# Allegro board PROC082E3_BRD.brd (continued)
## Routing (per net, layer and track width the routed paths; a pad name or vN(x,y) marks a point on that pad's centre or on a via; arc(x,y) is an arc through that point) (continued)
CSI_TX_D3_P: length 35
  TOP w0.102: v1(39.94,187.75) 39.92,187.75 arc(39.71,187.66) 39.62,187.45 39.62,186.72 arc(39.52,186.22) 39.24,185.8 arc(38.12,185.05) 36.79,184.78 35.97,184.78 arc(34.2,184.43) 32.7,183.43 28.18,178.91 arc(26.85,176.93) 26.39,174.59 26.39,171.31 arc(26.23,170.93) 25.85,170.77 25.69,170.77 arc(25.52,170.69) 25.44,170.52 v1(25.44,170.45)
  BOTTOM w0.102: v1(39.94,187.75) 39.85,187.75 arc(39.7,187.81) 39.64,187.96 39.64,188.16 arc(39.65,188.19) 39.67,188.23 39.73,188.28 arc(39.75,188.32) 39.76,188.36 J20.21 ; U32.29 28.85,165.81 arc(28.81,165.82) 28.78,165.84 28.72,165.9 arc(28.69,165.92) 28.65,165.93 28.5,165.93 arc(28.3,165.97) 28.13,166.08 27.2,167.01 arc(26.93,167.42) 26.84,167.89 26.84,170.13 arc(26.65,170.59) 26.19,170.77 25.62,170.77 arc(25.6,170.77) 25.59,170.77 arc(25.48,170.71) 25.44,170.6 v1(25.44,170.45)
DOUT_N: length 5.1
  BOTTOM w0.102: U32.13 35.01,165.31 arc(35.04,165.3) 35.08,165.28 35.13,165.22 arc(35.17,165.2) 35.21,165.19 38.39,165.19 arc(38.65,165.25) 38.87,165.39 C406.2
DOUT_P: length 5.1
  BOTTOM w0.102: C405.2 38.86,164.74 arc(38.65,164.88) 38.41,164.93 35.21,164.93 arc(35.17,164.92) 35.13,164.9 35.08,164.84 arc(35.04,164.82) 35.01,164.81 U32.14
EEPROM_A0: length 4
  BOTTOM w0.152: U20.1 10.32,89.36 10.2,89.23 R152.1 R151.2
EEPROM_A1: length 3.2
  BOTTOM w0.152: U20.2 R148.1 R149.2
EEPROM_A2: length 3.2
  BOTTOM w0.152: R146.2 R147.1 U20.3
EEPROM_WP: length 1.9
  BOTTOM w0.152: R153.2 U20.7
GPIO0_HUB1: length 5.1
  BOTTOM w0.152: R204.2 40.79,118.95 40.74,118.9 38.73,118.9 38.18,119.45 38.18,119.69 37.7,120.16 U9.6
GPIO0_HUB2: length 4.9
  BOTTOM w0.152: R202.2 42.99,54.52 42.72,54.78 42.72,56.62 43.83,57.72 U24.6
GPIO0_HUB3: length 4.2
  BOTTOM w0.152: R200.2 24.1,59.19 23.68,58.78 22.44,58.78 22.13,59.08 22.13,59.31 21.51,59.94 U25.6
GPIO1_HUB1: length 6.3
  BOTTOM w0.152: U9.7 37.62,119.66 37.84,119.44 37.84,119.24 38.66,118.41 41.93,118.41 42.46,118.95 R205.2
GPIO1_HUB2: length 6.3
  BOTTOM w0.152: R203.2 43,53.2 42.39,53.8 42.39,56.79 43.33,57.72 U24.7
GPIO1_HUB3: length 5.5
  BOTTOM w0.152: U25.7 21.54,59.44 21.77,59.21 21.77,58.85 22.22,58.4 24.59,58.4 25.14,58.95 R201.2
HUB1_CK_O: length 5.8
  BOTTOM w0.152: U9.14 37.67,116.16 38.12,116.61 41.74,116.61 41.87,116.74 TP11.1
HUB1_CMLOUT0N: length 8.3
  BOTTOM w0.102: TP9.1 14.55,124.66 14.69,124.8 15.96,124.8 17.67,123.1 19.37,123.1 R96.1 19.73,122.75 20.02,123.05 20.38,123.05 C181.1
HUB1_CMLOUT0P: length 8.4
  BOTTOM w0.102: TP10.1 14.55,125.21 14.69,125.07 16.07,125.07 17.78,123.37 19.38,123.37 R96.2 19.73,123.71 20.02,123.41 20.28,123.41 C179.1
HUB1_CMLOUT1N: length 4.6
  BOTTOM w0.102: C167.1 21.08,126.38 20.98,126.48 20.29,126.48 19.95,126.15 R82.1 19.88,126.15 19.52,126.5 18.4,126.5 18.23,126.33 TP4.1
HUB1_CMLOUT1P: length 4.5
  BOTTOM w0.102: C166.1 21.08,126.85 20.98,126.74 20.29,126.74 R82.2 19.86,127.13 19.51,126.77 18.37,126.77 18.23,126.9 TP3.1
HUB1_CMLOUT2N: length 6.5
  BOTTOM w0.102: C178.1 40.4,124.6 40.5,124.7 41.41,124.7 R94.1 41.82,124.34 42.17,124.7 42.77,124.7 43.03,124.96 43.03,125.57 43.43,125.97 44.17,125.97 44.27,125.87 TP6.1
HUB1_CMLOUT2P: length 6.5
  BOTTOM w0.102: TP5.1 44.27,126.34 44.17,126.24 43.32,126.24 42.76,125.68 42.76,125.07 42.66,124.97 42.19,124.97 41.83,125.32 R94.2 41.41,124.97 40.5,124.97 40.4,125.07 C171.1
HUB1_CMLOUT3N: length 5.7
  BOTTOM w0.102: C182.1 40.38,121.53 40.62,121.77 41.22,121.77 R98.1 41.61,121.41 41.97,121.77 42.95,121.77 43.11,121.61 44.15,121.61 44.26,121.5 44.26,120.63 TP8.1
HUB1_CMLOUT3P: length 5.6
  BOTTOM w0.102: TP7.1 44.26,121.97 44.15,121.87 43.22,121.87 43.06,122.04 41.96,122.04 41.61,122.39 R98.2 41.22,122.04 40.62,122.04 40.38,122.27 C180.1
HUB1_I2C_SCL2: length 4.8
  BOTTOM w0.152: R87.1 38.24,126.23 37.03,125.01 37.03,124.6 36.73,124.31 36.12,124.31 35.82,124.01 U9.87
HUB1_I2C_SDA2: length 5.2
  BOTTOM w0.152: U9.88 36.32,123.65 36.62,123.95 36.94,123.95 37.43,124.44 37.43,124.83 38.91,126.31 38.91,126.7 39.06,126.84 R86.1
HUB1_IDX: length 8.7
  TOP w0.152: R16.1 24.77,124.77 25.01,124.53 R15.2 v1(25.01,123.47)
  L6_SIG2 w0.102: v1(25.01,123.47) 25.95,123.47 27.22,124.74 29.83,124.74 v1(30.32,124.24)
  BOTTOM w0.152: v1(30.32,124.24) U9.76
HUB1_INTBN: length 106.8
  TOP w0.152: v1(53.42,35.31) 53.01,35.31 52.59,35.73 J2.6
  L03_SIG1 w0.102: v1(46.84,112.37) 45.16,114.05 45.16,114.63 41.38,118.41 39.25,118.41 v1(38.02,117.19)
  L6_SIG2 w0.102: v1(53.42,35.31) 56.64,38.53 56.64,45.48 56.04,46.08 56.04,47.57 56.64,48.18 56.64,67.69 61.77,72.82 61.77,74.73 62.41,75.36 62.41,86.92 58.63,90.69 56.86,90.69 48.54,99.01 48.54,100.79 46.15,103.17 46.15,106.81 46.84,107.49 v1(46.84,112.37)
  BOTTOM w0.152: U9.9 37.76,118.66 38.72,117.71 R99.1 v1(38.02,117.19)
HUB1_LPF: length 1.6
  TOP w0.152: v1(30.82,122.58) 30.82,122.29 30.89,122.22 C30.1
  BOTTOM w0.152: v1(30.82,122.58) 30.82,122.69 30.82,122.7 U9.77
HUB1_MODE: length 5.4
  TOP w0.152: R13.2 31.78,126.97 v1(32.02,126.73)
  BOTTOM w0.152: R88.1 31.83,126.92 v1(32.02,126.73) 32.48,126.27 32.48,124.57 31.82,123.91 U9.79
HUB1_REF CLK: length 58.7
  L6_SIG2 w0.102: v1(40.06,108.46) 40.06,107.04 36.51,103.49 28.36,103.49 v1(27.01,102.14)
  BOTTOM w0.152: U9.15 37.67,115.66 38.32,116.31 41.5,116.31 42.16,115.65 42.98,115.65 43.21,115.42 43.21,113.46 40.64,110.9 40.64,109.04 v1(40.06,108.46) ; v1(27.01,102.14) 25.11,102.14 21.49,98.52 20.99,98.52 19.79,97.32 19.79,96.69 16.78,93.69 16.78,85.95 14.28,83.44 R156.2
HUB1_REF CLK_R: length 2.6
  BOTTOM w0.152: U22.13 16.21,79.77 15.92,80.07 14.91,80.07 14.31,80.67 R156.1
HUB1_RIN0_N: length 8.7
  TOP w0.13: v1(28.03,128.04) 27.82,128.26 arc(27.79,128.3) 27.78,128.35 27.78,131.19 arc(27.84,131.34) 27.99,131.4 C132.2
  BOTTOM w0.13: v1(28.03,128.04) 27.82,127.83 arc(27.79,127.78) 27.78,127.74 27.78,123.45 U9.71
HUB1_RIN0_P: length 8.7
  TOP w0.13: v1(27.12,128.04) 27.33,128.26 arc(27.36,128.3) 27.37,128.35 27.37,131.19 arc(27.31,131.34) 27.16,131.4 C126.1
  BOTTOM w0.13: v1(27.12,128.04) 27.33,127.83 arc(27.36,127.78) 27.37,127.74 27.37,123.45 U9.70
HUB1_RIN1_N: length 9.2
  TOP w0.13: C160.2 31.09,131.3 arc(30.94,131.24) 30.88,131.09 30.88,129.67 arc(30.82,129.36) 30.65,129.1 30.15,128.6 arc(30.09,128.51) 30.07,128.41 30.07,128.22 arc(30.08,128.17) 30.11,128.13 v1(30.32,127.91)
  BOTTOM w0.13: v1(30.32,127.91) 30.18,127.77 arc(30.15,127.73) 30.14,127.68 30.14,126.88 30.14,125.21 arc(30.09,124.93) 29.93,124.69 29.36,124.13 arc(29.3,124.04) 29.28,123.93 29.28,123.45 U9.74
HUB1_RIN1_P: length 9.2
  TOP w0.13: v1(29.41,127.91) 29.62,128.13 arc(29.65,128.17) 29.66,128.22 29.66,128.41 arc(29.71,128.67) 29.86,128.89 30.36,129.39 arc(30.44,129.51) 30.47,129.67 30.47,131.06 arc(30.4,131.23) 30.24,131.3 C161.2
  BOTTOM w0.13: U9.73 28.87,123.45 28.87,123.93 arc(28.92,124.19) 29.07,124.42 29.64,124.98 arc(29.71,125.09) 29.73,125.21 29.73,126.88 29.73,127.34 arc(29.7,127.52) 29.59,127.67 29.44,127.82 arc(29.42,127.86) v1(29.41,127.91)
HUB1_RIN2_N: length 11.9
  TOP w0.13: v1(33.53,128.4) 33.42,128.4 arc(33.26,128.46) 33.19,128.62 33.19,130.29 arc(33.54,131.12) 34.38,131.47 36.26,131.47 arc(36.39,131.42) 36.44,131.29 C198.2
  BOTTOM w0.13: U9.82 33.24,123.49 33.24,128.36 arc(33.33,128.48) 33.47,128.45 v1(33.53,128.4)
HUB1_RIN2_P: length 12
  TOP w0.13: C190.1 36.44,132.19 arc(36.35,131.97) 36.12,131.88 34.38,131.88 arc(33.25,131.41) 32.79,130.29 32.79,128.8 arc(32.74,128.58) v1(32.62,128.4)
  BOTTOM w0.13: U9.81 32.83,123.42 32.83,127.93 arc(32.79,128.16) 32.66,128.36 v1(32.62,128.4)
HUB1_RIN3_N: length 9
  TOP w0.13: v1(35.03,126.95) 34.79,126.95 arc(34.69,126.99) 34.64,127.1 34.64,127.8 arc(34.84,128.28) 35.32,128.48 37.51,128.48 arc(37.65,128.42) 37.71,128.28 C218.1
  BOTTOM w0.13: U9.85 34.74,123.49 34.74,126.83 arc(34.85,126.99) v1(35.03,126.95)
HUB1_RIN3_P: length 9.1
  TOP w0.13: C219.1 37.71,129.09 arc(37.65,128.95) 37.5,128.89 35.32,128.89 arc(34.55,128.57) 34.23,127.8 34.23,127.23 arc(34.2,127.08) v1(34.12,126.95)
  BOTTOM w0.13: U9.84 34.33,123.41 34.33,126.55 arc(34.3,126.72) 34.2,126.87 v1(34.12,126.95)
HUB1_SYNC: length 113.6
  TOP w0.152: v1(56.41,34.95) 56.13,34.66 48.64,34.66 48.09,35.22 J2.18
  L03_SIG1 w0.102: v1(46.91,113.41) 41.55,118.77 36.68,118.77 v1(36.29,119.16)
  L6_SIG2 w0.102: v1(46.91,113.41) 47.45,112.88 47.45,107.7 46.46,106.71 46.46,103.45 49.3,100.61 49.3,98.75 57.02,91.03 58.85,91.03 62.81,87.07 62.81,73.28 59.66,70.12 59.66,65.63 58.22,64.19 58.22,61.34 57.73,60.86 57.73,36.27 v1(56.41,34.95)
  BOTTOM w0.152: v1(36.29,119.16) U9.8
HUB2_CK_O: length 6.5
  BOTTOM w0.152: TP26.1 40,52.89 40,57.56 39.83,57.73 U24.14
HUB2_CMLOUT0N: length 9.6
  BOTTOM w0.102: C249.1 45.8,75.05 45.9,75.16 45.9,76.03 R161.1 45.54,76.45 45.9,76.81 45.9,82.46 45.8,82.56 TP14.1
HUB2_CMLOUT0P: length 9.6
  BOTTOM w0.102: C248.1 46.27,75.05 46.17,75.16 46.17,76.03 R161.2 46.52,76.49 46.17,76.84 46.17,82.46 46.27,82.56 TP13.1
HUB2_CMLOUT1N: length 6.2
  BOTTOM w0.102: TP16.1 49.73,79.23 49.84,79.13 49.84,76.75 R160.1 49.84,76.03 49.84,75.16 49.73,75.05 C247.1
HUB2_CMLOUT1P: length 6.2
  BOTTOM w0.102: TP15.1 50.2,79.23 50.1,79.13 50.1,76.75 R160.2 50.1,76.03 50.1,75.16 50.2,75.05 C246.1
HUB2_CMLOUT2N: length 5.5
  BOTTOM w0.102: TP28.1 51.96,49.9 52.19,50.12 52.19,51.52 R185.1 52.19,52.24 52.19,53.4 52.09,53.5 C306.1
HUB2_CMLOUT2P: length 5.5
  BOTTOM w0.102: C305.1 52.56,53.5 52.46,53.4 52.46,52.24 R185.2 52.46,51.52 52.46,50.12 52.69,49.9 TP27.1
HUB2_CMLOUT3N: length 5.5
  BOTTOM w0.102: TP30.1 46.45,49.9 46.68,50.12 46.68,51.52 R186.1 46.68,52.24 46.68,53.4 46.58,53.5 C308.1
HUB2_CMLOUT3P: length 5.5
  BOTTOM w0.102: TP29.1 47.17,49.9 46.95,50.12 46.95,51.52 R186.2 46.95,52.24 46.95,53.4 47.05,53.5 C307.1
HUB2_I2C_SCL2: length 3.6
  BOTTOM w0.152: R176.1 48.65,57.99 48.19,58.46 48.19,59.34 47.97,59.57 U24.87
HUB2_I2C_SDA2: length 3.7
  BOTTOM w0.152: U24.88 47.63,59.07 47.79,58.91 47.79,58.23 49.19,56.83 R179.1
HUB2_IDX: length 13.3
  TOP w0.152: R34.1 52.32,71.66 R37.2 51.21,71.63 50.58,71 48.4,71 47.93,70.53 v1(47.93,64.51)
  BOTTOM w0.152: v1(47.93,64.51) 47.93,64.76 47.62,65.07 U24.76
HUB2_INTBN: length 30.6
  TOP w0.152: J2.8 v1(52.09,38.22)
  L6_SIG2 w0.102: v1(52.09,38.22) 51.41,38.9 48.24,38.9 46.8,40.34 46.8,51.48 41.51,56.76 v1(40.41,56.76)
  BOTTOM w0.152: U24.9 42.33,57.81 42.17,57.66 41.48,57.66 41.13,57.31 R180.1 v1(40.41,56.76)
HUB2_LPF: length 2.4
  TOP w0.254: v1(46.14,65.14) 46.19,65.18 C93.1
  BOTTOM w0.152: v1(46.14,65.14) 46.14,64.75 46.32,64.57 U24.77
HUB2_MODE: length 16
  TOP w0.152: v1(47.94,63.71) 47.95,63.71 48.33,64.1 48.33,68.29 48.65,68.6 53.21,68.6 54.52,69.91 54.52,71.58 54.37,71.73 R38.2 53.88,71.73 R35.1
  BOTTOM w0.152: U24.79 47.79,63.57 v1(47.94,63.71)
HUB2_REF CLK: length 45.7
  BOTTOM w0.152: R155.2 17.47,83.03 17.69,83.26 20.06,83.26 28.44,74.88 28.44,73.69 29.58,72.55 29.58,66.89 29.32,66.63 29.32,64.96 29.83,64.45 29.83,61.43 31.56,59.7 31.56,58.1 34.66,55 38.9,55 39.52,55.63 39.52,57.12 39.33,57.32 U24.15
HUB2_REF CLK_R: length 2
  BOTTOM w0.152: U22.15 17.21,80.69 17.47,80.94 R155.1
HUB2_SYNC: length 39.8
  TOP w0.152: J2.22 46.59,35.6 46.24,35.24 v1(43.55,35.24)
  BOTTOM w0.152: U24.8 42.83,57.72 42.06,56.96 42.06,50.77 41.29,50 36.21,50 35.27,49.06 35.27,38.74 38.77,35.24 v1(43.55,35.24)
HUB3_CK_O: length 4.5
  BOTTOM w0.152: U25.14 24.03,55.94 24.04,55.94 TP23.1
HUB3_CMLOUT0N: length 4.8
  BOTTOM w0.102: TP24.1 4.2,55.48 3.76,55.92 3.76,57.18 R177.1 3.76,57.9 3.76,58.51 3.98,58.72 C298.1
HUB3_CMLOUT0P: length 4.8
  BOTTOM w0.102: C299.1 3.28,58.72 3.5,58.51 3.5,57.9 R177.2 3.5,57.18 3.5,55.77 3.21,55.48 TP25.1
HUB3_CMLOUT1N: length 4.9
  BOTTOM w0.102: TP20.1 6.13,68.31 6.23,68.21 6.23,66.81 5.88,66.46 R174.1 5.88,66.32 6.23,65.96 6.23,65.19 6.13,65.09 C284.1
HUB3_CMLOUT1P: length 4.9
  BOTTOM w0.102: C283.1 6.6,65.09 6.5,65.19 6.5,65.98 6.86,66.34 R174.2 6.86,66.47 6.5,66.82 6.5,68.21 6.6,68.31 TP19.1
HUB3_CMLOUT2N: length 6.8
  BOTTOM w0.102: TP17.1 24.19,71.05 24.09,70.95 24.09,68.46 23.96,68.34 23.96,67.57 24.32,67.22 R173.1 23.96,66.81 23.96,66.45 24.49,65.92 C276.1
HUB3_CMLOUT2P: length 6.7
  BOTTOM w0.102: C277.1 23.7,66.51 23.7,66.81 R173.2 23.34,67.21 23.7,67.56 23.7,68.45 23.82,68.57 23.82,70.95 23.72,71.05 TP18.1
HUB3_CMLOUT3N: length 8.2
  BOTTOM w0.102: TP22.1 28.14,58.35 28.32,58.53 28.32,62.1 27.84,62.58 27.49,62.58 R175.1 26.78,62.58 26,62.58 25.89,62.48 C289.1
HUB3_CMLOUT3P: length 8.3
  BOTTOM w0.102: TP21.1 28.82,58.35 28.59,58.58 28.59,62.21 27.95,62.85 27.49,62.85 R175.2 26.78,62.85 26,62.85 25.89,62.95 C286.1
HUB3_I2C_SCL2: length 5.6
  BOTTOM w0.152: U25.87 19.85,63.92 20.31,64.38 20.91,64.38 21.24,64.71 21.24,67.35 R170.1
HUB3_I2C_SDA2: length 5.5
  BOTTOM w0.152: U25.88 20.35,63.79 20.58,64.02 21.1,64.02 21.64,64.56 21.64,67.24 22.06,67.66 R172.1
HUB3_IDX: length 3.1
  TOP w0.152: R171.2 13.03,61.39 13.2,61.56 R39.1 14.1,61.94 v1(14.1,62.33)
  BOTTOM w0.152: U25.76 14.35,62.58 v1(14.1,62.33)
HUB3_INTBN: length 122.4
  TOP w0.152: J1.8 v1(55.08,89.01)
  BOTTOM w0.152: U25.9 21.69,58.44 21.92,58.21 21.92,57.49 22.17,57.24 R178.1 22.66,56.72 23.03,56.35 24.52,56.35 25.27,57.1 29.08,57.1 30.3,55.87 30.3,54.83 32.24,52.89 32.24,40.42 38.26,34.4 59.04,34.4 62.08,37.44 62.08,37.8 64.35,40.07 64.35,85.21 60.54,89.01 v1(55.08,89.01)
HUB3_LPF: length 1.7
  TOP w0.152: C104.1 15.18,62.2 v1(15.03,62.35)
  BOTTOM w0.152: U25.77 14.85,62.53 v1(15.03,62.35)
HUB3_MODE: length 3.5
  TOP w0.152: v1(15.85,62.31) 15.85,61.9 16.12,61.63 R42.1 17.27,61.63 17.39,61.5 R41.2
  BOTTOM w0.152: U25.79 v1(15.85,62.31)
HUB3_REF CLK: length 35
  L03_SIG1 w0.102: v1(20,54.74) 19.17,55.57 19.17,58.8 23.79,63.41 23.79,69.06 22.69,70.16 22.69,80.43 20.87,82.25 v1(20.41,82.25)
  BOTTOM w0.152: v1(20,54.74) 20,55.2 20.23,55.44 U25.15 ; R154.2 20.17,82.4 20.32,82.25 v1(20.41,82.25)
HUB3_REF CLK_R: length 2.1
  BOTTOM w0.152: R154.1 18.57,80.94 18.21,80.59 U22.17
HUB3_SYNC: length 63.6
  TOP w0.152: v1(37.16,87.93) 37.77,88.54 50.23,88.54 51.08,89.39 J1.18
  L03_SIG1 w0.102: v1(27.16,87.43) 27.16,86.88 30.41,83.63 30.41,77.4 31.55,76.27 31.55,67.64 30.67,66.76 27.97,66.76 v1(20.14,58.94)
  L6_SIG2 w0.102: v1(27.16,87.43) 31.09,87.43 31.88,88.21 36.88,88.21 v1(37.16,87.93)
  BOTTOM w0.152: U25.8 v1(20.14,58.94)
HUB_RESETN: length 153.4
  TOP w0.152: C31.1 25.19,119.63 24.83,119.99 v1(24.13,119.99) 24.13,121.06 24.92,121.85 R17.2 ; J2.14 49.59,38.94 v1(49.09,39.44)
  L03_SIG1 w0.102: v1(8.13,59.61) 8.13,63.38 8.73,63.98 8.73,65.88 7.8,66.8 7.8,69.5 10.42,72.11 19.88,72.11 20.57,72.81 20.57,80.19 18.87,81.89 18.87,82.6 19.73,83.46 24.56,83.46 v1(26.62,85.52) 26.62,88.09 25.55,89.15 25.55,108.66 26.22,109.33 26.22,111 24.92,112.3 24.92,119.2 v1(24.13,119.99)
  L6_SIG2 w0.102: v1(42.89,74.03) 42.89,71.3 42.52,70.93 42.52,57.46 47.09,52.9 47.09,40.48 48.13,39.44 v1(49.09,39.44)
  BOTTOM w0.152: v1(26.62,85.52) 28.48,85.52 38.99,75.01 41.91,75.01 v1(42.89,74.03) 42.94,73.98 42.94,71.45 43.44,70.95 43.67,70.95 43.83,70.8 U24.61 ; v1(8.13,59.61) 8.21,59.61 8.54,59.94 U25.61 ; U9.61 24.3,120.16 v1(24.13,119.99)
LM25085A_FB: length 5.8
  TOP w0.305: R258.2 R259.1 52.23,7.3 C526.2 v1(50.29,8)
  BOTTOM w0.305: v1(50.29,8) 50.04,8 49.8,7.77 U35.3
LM25085A_ISEN: length 0.8
  BOTTOM w0.305: U35.5 50.3,3.92 50.42,3.81 50.93,3.81
  vias: v1(51.18,4.32) v1(52.07,5.21) v1(52.07,4.32) v1(52.07,2.41) v1(52.07,1.52) v1(52.96,5.21) v1(52.96,4.32) v1(52.96,2.41) v1(52.96,1.52) v1(53.85,5.21) v1(53.85,4.32) v1(53.85,2.41) v1(53.85,1.52) v1(54.99,1.52) v1(55.88,1.52) v1(56.77,1.52) v1(57.66,1.52) v1(58.55,1.52)
LPF1_CAP: length 2.3
  TOP w0.254: v1(35.27,168.1) 34.82,167.65 C408.1
  BOTTOM w0.254: v1(35.27,168.1) 34.83,167.66 34.83,167.47 34.67,167.31 U32.9
LPF2_CAP: length 3.8
  BOTTOM w0.152: U32.12 35.21,165.81 35.26,165.76 37.26,165.76 37.43,165.93 C407.1
OSC_REF CLK: length 1.5
  BOTTOM w0.152: R159.1 U21.3
R_971_REF CLK: length 2
  BOTTOM w0.152: U32.20 32.18,162.07 31.81,161.7 R236.2
RDR1_RIN_N: length 17.6
  BOTTOM w0.13: L19.3 48.68,164.36 arc(48.67,164.41) 48.64,164.45 48.5,164.59 arc(48.47,164.64) 48.46,164.69 48.46,165.96 arc(48.47,166.01) 48.5,166.05 48.71,166.26 arc(48.87,166.51) 48.93,166.79 48.93,167.05 U1.3 48.94,167.16 48.94,167.7 arc(49.1,168.48) 49.54,169.14 49.97,169.58 arc(50.94,170.22) 52.08,170.45 54.29,170.45 arc(54.47,170.37) 54.55,170.19 54.55,169.78 arc(54.81,169.53) 55.07,169.78 55.07,170.19 arc(55.33,170.45) 55.59,170.19 55.59,169.78 arc(55.85,169.53) 56.11,169.78 56.11,170.19 arc(56.18,170.37) 56.36,170.45 57.22,170.45 arc(57.53,170.39) 57.78,170.22 J3.4
RDR1_RIN_P: length 17.6
  BOTTOM w0.13: J3.2 59.29,171.01 arc(59.13,170.9) 58.93,170.86 52.08,170.86 arc(50.78,170.6) 49.68,169.86 49.25,169.43 arc(48.72,168.64) 48.53,167.7 48.53,167.16 U1.2 48.49,166.71 arc(48.47,166.63) 48.42,166.55 48.21,166.34 arc(48.09,166.16) 48.05,165.96 48.05,165.78 arc(48.03,165.7) U1.5 arc(48.03,165.56) 48.05,165.48 48.05,164.69 arc(48.04,164.64) 48.01,164.59 47.87,164.45 arc(47.84,164.41) 47.83,164.36 L19.2
RDR2_RIN_N: length 17.6
  BOTTOM w0.13: L21.3 48.66,142.77 arc(48.65,142.82) 48.63,142.86 48.48,143 arc(48.45,143.05) 48.44,143.1 48.44,144 U5.2 48.49,144.44 arc(48.51,144.53) 48.55,144.6 48.77,144.82 arc(48.88,144.99) 48.93,145.2 48.93,145.37 arc(48.94,145.45) U5.5 arc(48.94,145.59) 48.93,145.67 48.93,146.17 arc(49.07,146.88) 49.47,147.48 49.97,147.99 arc(50.94,148.63) 52.08,148.86 54.29,148.86 arc(54.47,148.78) 54.55,148.6 54.55,148.19 arc(54.81,147.94) 55.07,148.19 55.07,148.6 arc(55.33,148.86) 55.59,148.6 55.59,148.19 arc(55.85,147.94) 56.11,148.19 56.11,148.6 arc(56.18,148.78) 56.36,148.86 57.22,148.86 arc(57.53,148.8) 57.78,148.63 J6.4
RDR2_RIN_P: length 17.6
  BOTTOM w0.13: L21.2 47.81,142.77 arc(47.82,142.82) 47.85,142.86 48,143 arc(48.02,143.05) 48.03,143.1 48.03,144 U5.3 48.05,144.1 48.05,144.37 arc(48.1,144.65) 48.27,144.89 48.48,145.11 arc(48.51,145.15) 48.52,145.2 48.52,146.17 arc(48.69,147.04) 49.18,147.77 49.68,148.27 arc(50.78,149.01) 52.08,149.27 58.93,149.27 arc(59.13,149.31) 59.29,149.42 J6.2
RDR3_RIN_N: length 14.6
  BOTTOM w0.13: J9.4 58.99,127.53 arc(59.1,127.69) 59.14,127.89 59.14,134.46 arc(59.13,134.54) U10.5 arc(59.13,134.68) 59.14,134.76 59.14,134.94 arc(59.18,135.14) 59.3,135.32 59.51,135.53 arc(59.56,135.6) 59.58,135.69 U10.2 59.63,136.14 59.63,136.57 arc(59.04,137.98) 57.64,138.56 57.35,138.56 arc(57.3,138.55) 57.26,138.52 57.11,138.38 arc(57.07,138.35) 57.02,138.34 L22.3
RDR3_RIN_P: length 14.6
  BOTTOM w0.13: J9.2 59.9,128.92 arc(59.64,129.31) 59.55,129.76 59.55,130.26 arc(59.63,130.45) 59.81,130.52 59.93,130.52 arc(60.19,130.78) 59.93,131.04 59.81,131.04 arc(59.55,131.3) 59.81,131.56 59.88,131.56 arc(60.14,131.82) 59.88,132.08 59.81,132.08 arc(59.63,132.15) 59.55,132.34 59.55,134.94 arc(59.56,134.98) 59.59,135.03 59.8,135.24 arc(59.97,135.48) 60.02,135.77 60.02,136.03 U10.3 60.04,136.14 60.04,136.57 arc(59.33,138.27) 57.64,138.97 57.35,138.97 arc(57.3,138.98) 57.26,139.01 57.11,139.15 arc(57.07,139.18) 57.02,139.19 L22.2
RDR4_RIN_N: length 14.6
  BOTTOM w0.13: L24.3 57.02,116.75 arc(57.07,116.76) 57.11,116.79 57.26,116.93 arc(57.3,116.96) 57.35,116.97 57.64,116.97 arc(59.04,116.39) 59.63,114.98 59.63,114.55 U14.2 59.58,114.1 arc(59.56,114.01) 59.51,113.94 59.3,113.73 arc(59.18,113.55) 59.14,113.35 59.14,113.17 arc(59.13,113.09) U14.5 arc(59.13,112.95) 59.14,112.87 59.14,106.3 arc(59.1,106.1) 58.99,105.94 J12.4
RDR4_RIN_P: length 14.6
  BOTTOM w0.13: L24.2 57.02,117.6 arc(57.07,117.59) 57.11,117.56 57.26,117.42 arc(57.3,117.39) 57.35,117.38 57.64,117.38 arc(59.33,116.68) 60.04,114.98 60.04,114.55 U14.3 60.02,114.44 60.02,114.18 arc(59.97,113.89) 59.8,113.65 59.59,113.44 arc(59.56,113.39) 59.55,113.35 59.55,110.75 arc(59.63,110.56) 59.81,110.49 59.88,110.49 arc(60.14,110.23) 59.88,109.97 59.81,109.97 arc(59.55,109.71) 59.81,109.45 59.9,109.45 arc(60.16,109.19) 59.9,108.93 59.81,108.93 arc(59.63,108.86) 59.55,108.67 59.55,108.17 arc(59.64,107.72) 59.9,107.33 J12.2
REF_CLK: length 75.7
  TOP w0.152: v1(50.59,38.02) 51.09,37.52 J2.10
  BOTTOM w0.152: v1(50.59,38.02) 49.95,37.38 49.95,36.71 48.04,34.81 38.52,34.81 32.65,40.68 32.65,53.15 30.87,54.92 30.87,59.52 29.46,60.93 29.46,63.09 28.13,64.42 28.13,71.56 26.55,73.14 22.54,73.14 21.55,72.15 16.9,72.15 16.51,71.75 15.36,71.75 13.2,73.92 R165.1
REF_CLK_R: length 2.3
  BOTTOM w0.152: U22.9 14.26,77.27 14.2,77.21 R165.2
SOC_I2C6_SCL: length 256.5
  TOP w0.152: R47.2 v1(53.59,39.44) 54.09,38.94 J2.2
  L03_SIG1 w0.102: v1(12.74,87.49) 12.74,84.55 10.32,82.14 10.32,79.81 8.46,77.94 8.46,73.74 6.17,71.45 6.17,66.09 7.58,64.68 v1(8.27,64.68)
  L6_SIG2 w0.102: v1(49.82,71.87) 49.55,71.6 49.22,71.6 44.96,67.34 44.96,61.09 53.73,52.31 53.73,39.96 53.59,39.82 v1(53.59,39.44) 54.28,38.75 54.28,36.93 51.59,34.24 51.59,29.13 47.99,25.53 35,25.53 23.27,37.26 18.61,37.26 9.66,46.21 9.35,46.21 6.96,48.59 6.96,58.27 6.6,58.62 6.6,63.63 7.66,64.68 v1(8.27,64.68) ; v1(29.08,160.71) 29.08,153.74 33.37,149.45 33.37,133.33 31.51,131.47 27.9,131.47 25.15,128.71 25.15,125.83 25.73,125.25 v1(25.73,124.46) 25.51,124.24 24.44,124.24 22.73,122.54 22.73,120.84 23.13,120.45 23.13,117.87 22.53,117.27 22.53,113.19 22.73,112.99 22.73,112.33 22.35,111.94 22.35,106.23 21.94,105.83 21.94,94.2 20.37,92.62 20.06,92.62 17.57,90.14 16,90.14 13.35,87.49 v1(12.74,87.49)
  BOTTOM w0.152: v1(12.74,87.49) 12.86,87.36 U20.6 ; U24.68 47.52,69.07 47.84,69.39 47.84,70.29 49.41,71.87 v1(49.82,71.87) ; U9.68 26.32,123.86 v1(25.73,124.46) ; U32.24 30.18,162.82 29.88,162.52 29.64,162.52 29.08,161.96 v1(29.08,160.71) ; U25.68 10.35,63.67 9.8,64.22 8.73,64.22 v1(8.27,64.68)
SOC_I2C6_SDA: length 257.8
  TOP w0.152: R46.2 52.32,39.9 53.59,38.63 v1(53.59,38.22) J2.4
  L03_SIG1 w0.102: v1(8.29,65.41) 7.53,65.41 6.63,66.32 6.63,71.42 8.86,73.66 8.86,77.93 11.52,80.59 11.52,82.93 13,84.42 13,86.3 v1(14.13,87.43)
  L6_SIG2 w0.102: v1(29.64,159.92) 29.64,153.65 33.7,149.6 33.7,133.18 31.58,131.06 29.08,131.06 25.91,127.89 v1(25.68,127.89) 25.68,126.85 26.21,126.31 26.21,124.26 25.83,123.87 24.6,123.87 23.52,122.79 23.52,117.85 22.83,117.16 22.83,114.24 23.52,113.55 23.52,111.78 23.82,111.48 23.82,109.52 23.27,108.97 23.27,106.39 22.25,105.36 22.25,94.1 19.84,91.7 19.84,91.13 18.55,89.84 16.04,89.84 14.13,87.93 v1(14.13,87.43) ; v1(48.8,71.87) 48.8,71.49 44.46,67.14 44.46,60.79 43.92,60.25 43.92,57.67 44.78,56.81 45.07,56.81 52.74,49.14 52.74,39.07 v1(53.59,38.22) 53.59,37.77 50.67,34.85 50.67,33.12 49.89,32.33 49.38,32.33 48.62,31.57 48.62,28.88 45.52,25.78 36.02,25.78 24.03,37.77 18.74,37.77 9.78,46.74 9.25,46.74 7.21,48.77 7.21,58.39 6.81,58.8 6.81,63.32 7.62,64.14 8.38,64.14 8.71,64.47 8.71,64.99 v1(8.29,65.41)
  BOTTOM w0.152: v1(48.8,71.87) 47.08,70.14 U24.67 ; U25.67 9.85,63.67 9.7,63.83 8.45,63.83 7.83,64.45 7.83,64.95 v1(8.29,65.41) ; U32.23 30.68,162.46 30.22,162 29.9,162 29.64,161.75 v1(29.64,159.92) ; v1(14.13,87.43) 14.13,87.43 U20.5 ; v1(25.68,127.89) 25.17,127.38 25.17,124.3 25.82,123.65 U9.67
T_RDR1_RIN_N: length 43.6
  TOP w0.13: C125.2 v1(28.36,129.71)
  BOTTOM w0.13: v1(28.36,129.71) 28.05,129.71 arc(27.88,129.78) 27.8,129.95 27.8,132.44 arc(27.91,133) 28.23,133.47 32.84,138.08 arc(33.36,138.43) 33.96,138.55 34.65,138.55 arc(36.78,138.97) 38.58,140.17 42.97,144.56 arc(43.95,146.03) 44.3,147.77 44.3,153.42 arc(44.63,155.08) 45.57,156.49 47.22,158.14 arc(48.14,159.51) 48.46,161.13 48.46,161.72 arc(48.47,161.77) 48.5,161.81 48.64,161.96 arc(48.67,162) 48.68,162.05 L19.4
T_RDR1_RIN_P: length 43.7
  TOP w0.13: C126.2 v1(26.78,129.71)
  BOTTOM w0.13: L19.1 47.83,162.05 arc(47.84,162) 47.87,161.96 48.01,161.81 arc(48.04,161.77) 48.05,161.72 48.05,161.13 arc(47.76,159.67) 46.93,158.43 45.28,156.78 arc(44.25,155.24) 43.89,153.42 43.89,147.77 arc(43.58,146.19) 42.68,144.85 38.29,140.46 arc(36.62,139.35) 34.65,138.96 33.96,138.96 arc(33.2,138.8) 32.55,138.37 27.94,133.76 arc(27.54,133.15) 27.4,132.44 27.4,130.02 arc(27.3,129.8) 27.09,129.71 v1(26.78,129.71)
T_RDR2_RIN_N: length 27
  TOP w0.13: C151.2 v1(31.47,129.61)
  BOTTOM w0.13: v1(31.47,129.61) 31.18,129.61 arc(30.96,129.7) 30.87,129.91 30.87,132.27 arc(31.58,133.99) 33.3,134.7 44.17,134.7 arc(45.4,134.94) 46.44,135.64 48.02,137.22 arc(48.33,137.69) 48.44,138.24 48.44,140.13 arc(48.45,140.18) 48.48,140.22 48.63,140.37 arc(48.65,140.41) 48.66,140.46 L21.4
T_RDR2_RIN_P: length 27
  TOP w0.13: C154.2 v1(29.89,129.61)
  BOTTOM w0.13: v1(29.89,129.61) 30.13,129.61 arc(30.37,129.71) 30.47,129.94 30.47,132.27 arc(31.3,134.28) 33.3,135.11 44.17,135.11 arc(45.24,135.32) 46.15,135.93 47.73,137.51 arc(47.96,137.84) 48.03,138.24 48.03,140.13 arc(48.02,140.18) 48,140.22 47.85,140.37 arc(47.82,140.41) 47.81,140.46 L21.1
T_RDR3_RIN_N: length 24.1
  TOP w0.13: C189.2 v1(34.75,130.88)
  BOTTOM w0.13: v1(34.75,130.88) 34.75,131.02 arc(34.88,131.35) 35.21,131.48 43.89,131.48 arc(46.06,131.91) 47.9,133.14 53.04,138.28 arc(53.35,138.49) 53.71,138.56 54.38,138.56 arc(54.43,138.55) 54.48,138.52 54.62,138.38 arc(54.66,138.35) 54.71,138.34 L22.4
T_RDR3_RIN_P: length 24.1
  TOP w0.13: C190.2 v1(34.75,132.46)
  BOTTOM w0.13: v1(34.75,132.46) 34.75,132.28 arc(34.86,132) 35.14,131.89 35.14,131.89 arc(35.14,131.89) 35.15,131.89 35.15,131.89 arc(35.18,131.89) 35.21,131.89 43.89,131.89 arc(45.9,132.29) 47.61,133.43 52.75,138.57 arc(53.19,138.87) 53.71,138.97 54.38,138.97 arc(54.43,138.98) 54.48,139.01 54.62,139.15 arc(54.66,139.18) 54.71,139.19 L22.1
T_RDR4_RIN_N: length 29.5
  TOP w0.13: C218.2 v1(36.02,127.89)
  BOTTOM w0.13: L24.4 54.71,116.75 arc(54.66,116.76) 54.62,116.79 54.48,116.93 arc(54.43,116.96) 54.38,116.97 52.65,116.97 arc(50.07,118.04) 49,120.62 49,124.95 arc(47.69,128.11) 44.54,129.42 38.51,129.42 arc(37.95,129.31) 37.47,128.99 37.3,128.81 arc(36.91,128.55) 36.45,128.46 36.2,128.46 arc(36.07,128.41) 36.02,128.28 v1(36.02,127.89)
T_RDR4_RIN_P: length 29.5
  TOP w0.13: C219.2 v1(36.02,129.47)
  BOTTOM w0.13: v1(36.02,129.47) 36.02,129.15 arc(36.1,128.95) 36.29,128.87 36.45,128.87 arc(36.75,128.93) 37.01,129.1 37.18,129.28 arc(37.79,129.68) 38.51,129.83 44.54,129.83 arc(47.98,128.4) 49.41,124.95 49.41,120.62 arc(50.36,118.33) 52.65,117.38 54.38,117.38 arc(54.43,117.39) 54.48,117.42 54.62,117.56 arc(54.66,117.59) 54.71,117.6 L24.1
TESTEN1: length 3
  TOP w0.152: R22.1 27.13,119.15 v1(26.37,119.91)
  BOTTOM w0.152: U9.60 25.7,119.66 25.96,119.91 v1(26.37,119.91)
TESTEN2: length 1.8
  TOP w0.152: R36.1 43.25,69.21 v1(43.33,69.29)
  BOTTOM w0.152: U24.60 v1(43.33,69.29)
TESTEN3: length 2.1
  TOP w0.152: v1(10.09,59.32) 10.28,59.13 R43.1
  BOTTOM w0.152: U25.60 9.98,59.44 v1(10.09,59.32)
TP_CLKOUT1: length 3
  BOTTOM w0.152: U22.5 16.71,73.61 TP50.1
V_CAM5: length 1.2
  BOTTOM w0.305: 73.97,85.5 74.39,85.92 U18.8
  vias: v1(67.57,85.14) v1(67.57,84.13)
V_CAM6: length 1.5
  BOTTOM w0.305: 73.7,66.15 74.16,66.61 U23.8
  vias: v1(67.57,65.97) v1(67.57,64.95)
V_CAM7: length 1.2
  BOTTOM w0.305: 73.97,46.72 74.41,47.16 U26.8
  vias: v1(66.71,46.16) v1(66.71,45.14)
V_CAM8: length 1.2
  BOTTOM w0.305: U27.8 74.41,28.31 73.97,27.87
  vias: v1(66.41,26.46) v1(67.42,26.46)
V_CAM9: length 1.4
  BOTTOM w0.305: U16.8 8.78,96.98 9.3,97.5
  vias: v1(13.92,98.68) v1(14.67,98.71)
V_CAM10: length 1.4
  BOTTOM w0.305: U12.8 8.78,118.65 9.3,119.17
  vias: v1(15.73,119.67) v1(15.78,120.47)
V_CAM11: length 1.5
  BOTTOM w0.305: U7.8 8.95,139.58 9.43,140.07
  vias: v1(15.73,141.77) v1(15.78,142.57)
V_CAM12: length 1.5
  BOTTOM w0.305: 9.43,163.56 8.92,163.05 U3.8
  vias: v1(15.73,163.87) v1(15.78,164.66)
V_RAD/CAM1: length 1.1
  BOTTOM w0.305: U4.8 74.56,164.45 74.09,163.98
  vias: v1(66.41,163.64) v1(66.41,162.87) v1(66.41,162.11) v1(67.17,163.64) v1(67.17,162.87) v1(67.17,162.11) v1(67.93,163.64) v1(67.93,162.87) v1(67.93,162.11)
V_RAD/CAM1_CON1: length 15.4
  BOTTOM w0.229: 47.75,167.54 47.99,167.3 U1.1
  BOTTOM w0.305: 47.75,167.54 47.48,167.8
  BOTTOM w0.381: 47.48,167.8 47.48,170.58 49.37,172.47 55.37,172.47 55.98,171.86 J3.1
V_RAD/CAM2: length 1.1
  BOTTOM w0.305: 74.1,144.36 74.56,144.82 U8.8
  vias: v1(66.3,144.33) v1(66.3,143.57) v1(66.3,142.81) v1(67.32,144.33) v1(67.32,143.57) v1(67.32,142.81) v1(68.34,144.33) v1(68.34,143.57) v1(68.34,142.81)
V_RAD/CAM2_CON3: length 13.5
  BOTTOM w0.229: U5.1 48.99,144.18 arc(49.02,144.3) 49.11,144.38
  BOTTOM w0.305: 49.55,144.61 49.11,144.38
  BOTTOM w0.381: J6.3 60.14,147.36 57.39,144.61 49.55,144.61
V_RAD/CAM3: length 1
  BOTTOM w0.305: U13.8 74.41,124.78 74.08,124.44
  vias: v1(66.07,123.98) v1(66.07,123.22) v1(66.07,122.46) v1(66.83,124.21) v1(66.83,123.45) v1(66.83,122.68) v1(67.6,124.21) v1(67.6,123.45) v1(67.6,122.68)
V_RAD/CAM3_CON1: length 8.2
  BOTTOM w0.229: U10.1 59.08,135.88 58.85,135.65
  BOTTOM w0.305: 58.85,135.65 58.55,135.35 58.48,135.35
  BOTTOM w0.381: 58.48,135.35 57.74,134.6 57.74,130.33 58.14,129.93 J9.1
V_RAD/CAM4: length 1.5
  BOTTOM w0.305: 73.69,104.62 74.3,105.23 U17.8
  vias: v1(67.63,105.42) v1(67.63,104.66) v1(67.63,103.9) v1(67.63,103.13) v1(68.36,105.42) v1(68.36,104.66) v1(68.36,103.9) v1(68.36,103.14)
V_RAD/CAM4_CON1: length 8.2
  BOTTOM w0.229: 58.85,114.06 59.08,114.29 U14.1
  BOTTOM w0.305: 58.85,114.06 58.55,113.76 58.48,113.76
  BOTTOM w0.381: 58.48,113.76 57.74,113.01 57.74,108.74 58.14,108.34 J12.1
VCC_1V1_RT/CLK: length 3.2
  BOTTOM w0.254: U33.8 16.25,21.06 15.91,20.72 15.14,20.72 14.86,20.45 14.86,19.93 14.29,19.36 R241.1
VCC_1V1_SS/TR: length 1.9
  BOTTOM w0.254: U33.9 14.48,22.04 14.02,21.58 C500.1
VIO_CLK_OSC: length 14.1
  TOP w0.381: C251.1 19.65,81.65 v1(19.63,81.67)
  BOTTOM w0.254: U21.4 7.79,77.21 7.75,77.25 R158.1
  BOTTOM w0.305: U22.18 18.71,79.92 C252.1 ; v1(15.33,80.66) C242.1 16.41,80.66 16.71,80.35 U22.14
  BOTTOM w0.381: FL60.2 8.03,75.84 v1(7.67,76.2) ; FL60.2 8.04,75.44 C245.1 U21.4 ; FL60.2 8.03,74.76 v1(7.88,74.61) ; v1(21.79,74.14) 21.79,74.05 21.41,73.67 R167.2 ; R157.2 v1(21.17,79.46) ; v1(19.63,81.67) C252.1
VMAIN: length 1.5
  BOTTOM w0.305: U35.8 48.8,3.97 48.26,3.43 v1(47.62,3.43)
  vias: v1(28.32,12.6) v1(28.32,10.82) v1(28.77,11.71) v1(28.77,9.93) v1(29.21,12.6) v1(29.21,10.82) v1(29.21,9.17) v1(29.65,11.71) v1(29.65,9.93) v1(30.1,12.6) v1(30.1,10.82) v1(30.1,9.14) v1(30.54,11.71) v1(30.54,9.93) v1(30.99,12.6) v1(30.99,10.82) v1(43.56,7.39) v1(43.56,5.61) v1(44.01,8.28) v1(44.01,6.5) v1(44.01,4.72) v1(44.45,7.39) v1(44.45,5.61) v1(44.89,8.28) v1(44.89,6.5) v1(44.89,4.72) v1(45.34,7.39) v1(45.34,5.61) v1(45.34,3.81) v1(45.78,8.28) v1(45.78,6.5) v1(45.78,4.72) v1(46.1,7.37) v1(46.1,5.59) v1(46.23,3.81)
VREG_3V3: length 31.6
  TOP w0.254: U29.4 44.7,104.15 45.1,103.75 C355.1 ; C358.1 24.73,28.42 U30.4 ; U31.4 14.17,29.59 C361.1 ; C518.1 13.17,30.15 U31.2
  L03_SIG1 w0.381: v1(42.04,19.18) 28.14,19.18 v1(22.71,24.61)
  BOTTOM w0.203: 17.75,24.68 U33.16
  BOTTOM w0.254: R199.1 v1(42.04,19.18) ; 19.13,23.04 U33.2
  BOTTOM w0.305: 18.06,25.02 17.75,24.71 17.75,24.68 ; 19.5,23.04 19.13,23.04
  vias: v1(20.68,26.64) v1(20.68,25.63) v1(20.68,24.61) v1(20.68,23.6) v1(21.69,26.64) v1(21.69,25.63) v1(21.69,24.61) v1(21.69,23.6) v1(22.71,26.64) v1(22.71,25.63) v1(38.25,102.72) v1(38.25,101.96) v1(39.01,102.72) v1(39.01,101.96)
VREG_3V3_CBOOT: length 2.2
  BOTTOM w0.254: U28.13 37.67,22.36 37.16,22.87 37.16,23.38 36.71,23.84 C338.1
VREG_3V3_COMP: length 3.3
  BOTTOM w0.254: U28.8 38.92,19.36 38.61,19.04 38.15,19.04 37.96,18.85 C345.1 37.64,17.96 R196.1
VREG_3V3_EN: length 5.8
  BOTTOM w0.254: R253.2 R254.1 35.41,17.64 36.04,18.28 36.04,19.74 37.17,20.86 U28.10
VREG_3V3_FB: length 2.6
  BOTTOM w0.254: U28.7 40.42,19.07 R199.2 R198.1
VREG_3V3_PG: length 2.1
  BOTTOM w0.152: TP32.1 38.92,24.46 U28.14
VREG_3V3_RT/CLK: length 2
  BOTTOM w0.203: R193.1 40.67,24.52 40.42,24.28 U28.1
VREG_3V3_SS/TR: length 3.7
  BOTTOM w0.254: C350.1 36.52,19.62 37.25,20.36 U28.9
VREG_3V3_SW: length 5.8
  BOTTOM w0.254: C338.2 35.99,24.82 35.74,24.56 35.74,22.66
  BOTTOM w0.305: U28.12 36.94,21.86 36.73,22.07 ; 36.5,21.03 36.83,21.36 U28.11
N23311355: length 4.7
  BOTTOM w0.152: U4.20 79.44,163.95 79.66,163.73 79.66,161.77 79.42,161.53 R71.2
N23312712: length 2.6
  BOTTOM w0.152: U4.14 77.22,166.77 77,166.99 R64.2 R63.1
N23312989: length 3.6
  BOTTOM w0.152: U4.15 77.72,166.72 77.88,166.88 79.03,166.88 79.19,167.03 R63.2 R62.1
N23313210: length 1.2
  BOTTOM w0.152: C139.1 80.2,164.95 U4.18
N23313421: length 1.8
  BOTTOM w0.152: R65.1 80.21,165.92 79.74,165.45 U4.17
N23314293: length 2
  BOTTOM w0.152: U4.19 79.76,164.45 80.21,164.01 R70.1
N23315548: length 2.6
  BOTTOM w0.152: R84.1 R85.2 77,147.38 77.22,147.16 U8.14
N23315552: length 3.6
  BOTTOM w0.152: R83.1 R84.2 79.19,147.4 79.03,147.25 77.88,147.25 77.72,147.09 U8.15
N23315587: length 1.2
  BOTTOM w0.152: U8.18 80.2,145.32 C170.1
N23315604: length 1.8
  BOTTOM w0.152: U8.17 79.74,145.82 80.21,146.28 R89.1
N23315632: length 2
  BOTTOM w0.152: U8.19 79.76,144.82 80.21,144.37 R95.1
N23315748: length 4.7
  BOTTOM w0.152: R97.2 79.42,141.9 79.66,142.14 79.66,144.1 79.44,144.32 U8.20
N23316320: length 2.6
  BOTTOM w0.152: U13.14 77.22,127.12 77,127.34 R110.2 R109.1
N23316340: length 3.6
  BOTTOM w0.152: U13.15 77.72,127.04 77.88,127.2 79.03,127.2 79.19,127.36 R109.2 R108.1
N23316375: length 1.2
  BOTTOM w0.152: U13.18 80.2,125.28 C213.1
N23316392: length 1.8
  BOTTOM w0.152: R111.1 80.21,126.24 79.74,125.78 U13.17
N23316420: length 2
  BOTTOM w0.152: R116.1 80.21,124.33 79.76,124.78 U13.19
N23316528: length 4.7
  BOTTOM w0.152: U13.20 79.44,124.28 79.66,124.06 79.66,122.1 79.42,121.86 R118.2
N23317098: length 2.6
  BOTTOM w0.152: U17.14 77.22,107.65 76.62,108.26 R123.2 R122.1
N23317110: length 3.5
  BOTTOM w0.152: R125.1 79.6,108.17 79.47,108.29 R122.2 78.68,107.86 78.47,107.65 77.83,107.65 77.72,107.55 U17.15
N23317144: length 1.2
  BOTTOM w0.152: C230.1 79.96,105.73 U17.18
N23317167: length 1.7
  BOTTOM w0.152: R129.1 80.08,106.43 79.88,106.23 U17.17
N23317190: length 1.8
  BOTTOM w0.152: U17.19 79.39,105.23 80.08,104.55 R137.1
N23317306: length 3.6
  BOTTOM w0.152: R144.2 78.82,102.31 78.97,102.47 U17.20
N23319711: length 2.6
  BOTTOM w0.152: R131.1 R132.2 77,88.4 77.22,88.18 U18.14
N23319731: length 3.6
  BOTTOM w0.152: R130.1 R131.2 79.19,88.5 79.03,88.34 77.88,88.34 77.72,88.18 U18.15
N23319762: length 1.2
  BOTTOM w0.152: C233.1 80.2,86.42 U18.18
N23319779: length 1.8
  BOTTOM w0.152: R135.1 80.21,87.38 79.74,86.92 U18.17
N23319811: length 2
  BOTTOM w0.152: U18.19 79.76,85.92 80.21,85.47 R141.1
N23319923: length 4.7
  BOTTOM w0.152: R150.2 79.42,83 79.66,83.24 79.66,85.19 79.44,85.42 U18.20
N23320313: length 2.6
  BOTTOM w0.152: R163.1 R164.2 77,69.2 77.22,68.98 U23.14
N23320339: length 3.6
  BOTTOM w0.152: U23.15 77.72,68.88 77.88,69.04 79.03,69.04 79.19,69.19 R163.2 R162.1
N23320379: length 1.2
  BOTTOM w0.152: U23.18 80.2,67.11 C253.1
N23320395: length 1.8
  BOTTOM w0.152: R166.1 80.21,68.08 79.74,67.61 U23.17
N23320426: length 2
  BOTTOM w0.152: U23.19 79.76,66.61 80.21,66.17 R168.1
N23320539: length 4.7
  BOTTOM w0.152: U23.20 79.44,66.11 79.66,65.89 79.66,63.93 79.42,63.69 R169.2
N23320826: length 2.6
  BOTTOM w0.152: U26.14 77.22,49.52 77,49.75 R183.2 R182.1
N23320852: length 3.6
  BOTTOM w0.152: R181.1 R182.2 79.19,49.74 79.03,49.59 77.88,49.59 77.72,49.43 U26.15
N23320892: length 1.2
  BOTTOM w0.152: U26.18 78.98,47.67 C312.1
N23320908: length 1.8
  BOTTOM w0.152: U26.17 79.74,48.16 80.21,48.63 R184.1
N23320939: length 2
  BOTTOM w0.152: U26.19 79.76,47.16 80.21,46.72 R187.1
N23321052: length 4.7
  BOTTOM w0.152: R188.2 79.42,44.24 79.66,44.49 79.66,46.44 79.44,46.66 U26.20
N23321397: length 2.6
  BOTTOM w0.152: U27.14 77.22,30.65 77,30.87 R191.2 R190.1
N23321423: length 3.6
  BOTTOM w0.152: R189.1 R190.2 79.19,30.89 79.03,30.74 77.88,30.74 77.72,30.58 U27.15
N23321463: length 1.2
  BOTTOM w0.152: U27.18 78.98,28.82 C339.1
N23321479: length 1.8
  BOTTOM w0.152: R192.1 80.21,29.77 79.74,29.31 U27.17
N23321510: length 2
  BOTTOM w0.152: U27.19 79.76,28.31 80.21,27.86 R194.1
N23321623: length 4.7
  BOTTOM w0.152: R195.2 79.42,25.39 79.66,25.63 79.66,27.59 79.44,27.81 U27.20
N23545556: length 2.6
  BOTTOM w0.152: R139.1 R138.2 6.08,94.43 5.86,94.65 U16.14
N23545576: length 3.6
  BOTTOM w0.152: R140.1 R139.2 3.89,94.4 4.05,94.56 5.2,94.56 5.36,94.72 U16.15
N23545607: length 1.2
  BOTTOM w0.152: C231.1 2.88,96.48 U16.18
N23545624: length 1.8
  BOTTOM w0.152: U16.17 3.34,95.98 2.87,95.52 R136.1
N23545648: length 2
  BOTTOM w0.152: R128.1 2.87,97.43 3.32,96.98 U16.19
N23545749: length 4.7
  BOTTOM w0.152: R121.2 3.66,99.9 3.42,99.66 3.42,97.71 3.64,97.48 U16.20
N23545784: length 2.6
  BOTTOM w0.152: R114.1 R113.2 6.08,116.07 5.86,116.29 U12.14
N23545810: length 3.6
  BOTTOM w0.152: U12.15 5.36,116.38 5.2,116.22 4.05,116.22 3.89,116.07 R114.2 R115.1
N23545851: length 1.2
  BOTTOM w0.152: C210.1 2.88,118.15 U12.18
N23545860: length 1.8
  BOTTOM w0.152: U12.17 3.34,117.65 2.87,117.18 R112.1
N23545892: length 2
  BOTTOM w0.152: U12.19 3.32,118.65 2.87,119.1 R106.1
N23546004: length 4.7
  BOTTOM w0.152: U12.20 3.64,119.15 3.42,119.37 3.42,121.33 3.66,121.57 R102.2
N23546024: length 2.6
  BOTTOM w0.152: R92.1 R91.2 6.08,137 5.86,137.22 U7.14
N23546050: length 3.6
  BOTTOM w0.152: U7.15 5.36,137.31 5.2,137.15 4.05,137.15 3.89,137 R92.2 R93.1
N23546087: length 1.2
  BOTTOM w0.152: U7.18 4.1,139.07 C164.1
N23546094: length 1.8
  BOTTOM w0.152: R90.1 2.87,138.11 3.34,138.58 U7.17
N23546126: length 2
  BOTTOM w0.152: U7.19 3.32,139.58 2.87,140.03 R81.1
N23546235: length 4.7
  BOTTOM w0.152: U7.20 3.64,140.08 3.42,140.3 3.42,142.26 3.66,142.5 R78.2
N23546420: length 2.6
  BOTTOM w0.152: R68.1 R67.2 6.08,160.42 5.86,160.64 U3.14
N23546459: length 3.6
  BOTTOM w0.152: R69.1 R68.2 3.89,160.47 4.05,160.62 5.2,160.62 5.36,160.78 U3.15
N23546547: length 1.2
  BOTTOM w0.152: C136.1 4.1,162.54 U3.18
N23546577: length 1.8
  BOTTOM w0.152: U3.17 3.34,162.05 2.87,161.58 R66.1
N23546608: length 2
  BOTTOM w0.152: R61.1 2.87,163.5 3.32,163.05 U3.19
N23546717: length 4.7
  BOTTOM w0.152: R57.2 3.66,165.97 3.42,165.73 3.42,163.77 3.64,163.55 U3.20
N23898061: length 2.1
  BOTTOM w0.152: U21.1 8.55,78.76 8.02,78.23 R158.2
N24518728: length 1.1
  BOTTOM w0.254: C348.1 R196.2
N24522043: length 1.1
  BOTTOM w0.254: R244.2 C501.1
N24763505: length 14
  L04_PWR1 w0.381: v1(61.52,2.21) 60.43,3.3 v1(49.91,3.3)
  BOTTOM w0.305: v1(49.91,3.3) 49.8,3.41 U35.6 ; U36.4 v1(61.52,2.21)
N24766225: length 2.4
  TOP w0.305: R257.2 50.06,8.53 49.66,8.13 v1(49.3,8.13)
  BOTTOM w0.305: v1(49.3,8.13) U35.2
N24772813: length 4
  TOP w0.305: v1(48.26,7.11) 48.26,8.18 49.02,8.94 R256.1
  BOTTOM w0.305: v1(48.26,7.11) 48.27,7.1 U35.1 48.8,7.7 C523.2
N24774750: length 2
  TOP w0.305: v1(49.15,3.3) 48.97,3.3 48.67,3.61 C522.1
  BOTTOM w0.305: U35.7 49.3,3.46 v1(49.15,3.3)

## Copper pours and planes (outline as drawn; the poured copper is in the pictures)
DGND on BOTTOM (solid shape): 12.43,41.03 10.49,41.03 10.49,41.41 10.57,41.41 10.57,42.55 12.43,42.55
DGND on BOTTOM (solid shape): 27.87,35.86 26.68,35.86 26.68,37.3 27.32,37.3 27.32,37.5 27.87,37.5
DGND on BOTTOM (solid shape): 28.1,41.22 28.1,40.4 27.32,40.4 27.32,40.57 26.58,40.57 26.58,41.45 26.83,41.71 27.62,41.71
DGND on TOP: 28.79,82.75 28.79,79.49 31.13,79.49 31.13,82.75
DGND on TOP: 15.6,28.65 17.3,28.65 17.58,28.93 19.2,28.93 19.58,29.31 22.07,29.31 22.48,29.72 22.48,30.4 22.83,30.76 25.91,30.76 25.91,32 26.09,32.18 26.09,32.87 25.91,33.05 25.1,33.05 25.1,32.46 24.82,32.18 19.76,32.18 19.53,32.41 19.53,33.71 19.25,33.99 17.32,33.99 17.12,33.78 17.12,30.89 16.36,30.12 15.57,30.12 15.57,28.68
DGND on TOP: 11.25,25.96 11.25,27.64 11.76,28.14 11.91,28.14 11.91,31.52 12.29,31.9 15.19,31.9 15.19,33.25 14.83,33.6 14.83,34.21 14.81,34.24 14.53,34.24 14.53,33.5 14.43,33.4 8.89,33.4 8.89,25.96
DGND on TOP: 28.66,77.15 28.66,74.15 30.9,74.15 30.9,77.15
DGND on TOP: 1.02,1.02 1.02,189.48 82.14,189.48 82.14,1.02 ; 17 cut-outs
DGND on TOP: 38.47,83.22 38.47,80.3 40.75,80.3 40.75,83.22
DGND on TOP: 46.37,8.93 46.95,8.34 46.95,7.55 47.8,7.55 47.8,10.41 47.06,11.16 45.82,11.16 45.82,10.41 46.37,10.41
DGND on TOP: 9.8,36.14 9.8,37.41 10.16,37.77 15.04,37.77 15.42,37.39 15.42,35.94 13.72,35.94 13.64,36.02 13.64,36.58 13.39,36.83 12.06,36.83 11.76,36.53 11.76,36.14
DGND on BOTTOM: 8.14,37.12 8.14,38.89 6.39,38.89 6.39,37.12
DGND on BOTTOM: 22.1,44.53 22.1,45.97 20.73,45.97 20.73,44.53
DGND on BOTTOM: 15.5,41.07 17.35,41.07 17.35,42.94 15.5,42.94
DGND on L02_GND1: 1.02,189.48 82.14,189.48 82.14,1.02 1.02,1.02 ; 4 cut-outs
DGND on L03_SIG1: 1.02,1.02 1.02,189.48 82.14,189.48 82.14,1.02 ; 5 cut-outs
DGND on L04_PWR1: 1.02,1.02 1.02,189.48 82.14,189.48 82.14,1.02 ; 9 cut-outs
DGND on L5_GND2: 1.02,189.48 82.14,189.48 82.14,1.02 1.02,1.02 ; 4 cut-outs
DGND on L6_SIG2: 1.02,189.48 82.14,189.48 82.14,1.02 1.02,1.02 ; 8 cut-outs
DGND on L7_GND3: 1.02,1.02 1.02,189.48 32.95,189.48 32.95,188.38 46.05,188.38 46.05,189.48 82.14,189.48 82.14,1.02 ; 6 cut-outs
VCC_1V1 on BOTTOM: 24.95,140.22 34.11,140.22 36,142.11 36,151.69 33.47,151.69 33.47,150.26 33.49,150.25 33.49,147.43 32.73,146.67 32.73,143.49 32.6,143.37 28.2,143.37 28.2,143.39 27.65,143.95 27.65,147.13 24.71,147.13 24.71,140.46
VCC_1V1 on BOTTOM: 5.59,22.71 5.59,34.75 7.75,34.75 7.75,41.66 21.17,41.66 21.17,52.15 26.58,52.15 26.58,50.94 25.93,50.29 25.93,48.78 26.58,48.13 26.58,46.85 25.88,46.15 25.88,44.64 26.7,43.83 26.7,42.47 25.94,41.72 25.94,39.94 26.68,39.94 26.68,37.93 26.05,37.93 26.05,36.12 14.38,36.12 14.38,28.16 13.23,28.16 13.23,26.67 13,26.67 13,22.71
VCC_1V1 on L6_SIG2: 1.1,27.84 1.1,102.14 9.94,102.14 11.25,103.45 11.25,144.28 30.35,144.28 30.35,141.67 21.68,132.99 21.68,96.35 6.32,81 6.32,47.12 10.59,42.85 10.59,27.84 ; 1 cut-out
VCC_1V1_SW on BOTTOM: 15.49,26.37 13.11,26.37 13.11,22.3 15.54,22.3 15.54,24.28 15.49,24.33
VCC_1V8 on TOP: 25.27,74.71 25.27,86.79 23.74,88.33 23.74,91.71 26.53,94.5 26.53,99.81 25.45,100.89 24.08,100.89 24.08,105.29 30.73,105.29 32.4,103.62 32.4,94.38 35.14,91.63 35.14,86.34 37.12,84.36 37.12,78.6 37.3,78.42 37.3,77.28 32.75,77.28 32.75,83.42 32.29,83.88 28.76,83.88 28.02,83.13 28.02,71.58 26.11,71.58 25.65,71.12 25.65,68.59 22.98,68.59 22.98,71.14 23.72,71.89 23.72,73.7 24.26,73.7
VCC_1V8 on BOTTOM: 23.83,132.88 22.41,132.88 21.72,133.56 21.72,138.92 23.83,138.92
VCC_1V8 on BOTTOM: 23.79,88.04 23.17,88.65 23.17,97.82 24.84,99.49 28.02,99.49 28.02,93.68 27.48,93.14 27.48,88.52 27,88.04
VCC_1V8 on L03_SIG1: 15.9,76.43 14.39,74.93 14.39,73 15.29,72.1 18.96,72.1 20.23,73.38 20.23,80.24 18.59,81.88 18.59,84.37 21.28,87.06 25.02,87.06 25.25,87.29 25.25,97.67 21.5,101.41 21.5,133.38 25.32,137.2 25.32,153.36 29.43,157.48 36.66,157.48 39.78,160.59 39.78,167.64 36.25,171.17 25.85,171.17 15.9,161.21
VCC_1V8_SW on BOTTOM: 31.42,92.96 30.87,93.51 30.67,93.51 30.58,93.6 30.58,99.49 32.64,99.49 32.64,93.76 32.42,93.53 32.37,93.53 31.8,92.96
VCC_3V3 on TOP: 44.36,89.65 46.77,89.65 46.77,91.55 48.16,91.55 48.41,91.81 48.41,94.21 46.1,94.21 46.1,94.72 44.55,94.72 44.04,95.22 44.04,96.93 43.48,97.49 40.03,97.49 40.03,95.89 42.14,93.78 42.14,93.45 42.76,92.82 44.23,92.82 44.36,92.69
VCC_3V3 on TOP: 44.18,36 41.39,36 41.39,38.77 41.22,38.77 41.22,41.91 44.2,41.91 44.2,41.16 44.18,41.14
VCC_3V3 on BOTTOM: 38.14,36.66 38.14,48.88 57.95,48.88 57.95,73.21 47.84,83.32 41.49,83.32 41.49,89.32 41.17,89.64 31.95,89.64 31.95,92.86 37.77,92.86 38.07,93.16 48.06,93.16 53.64,87.59 55.71,87.59 64.58,78.72 64.58,36.66 ; 2 cut-outs
VCC_12V on BOTTOM (solid shape): 76.31,30.76 76.36,30.71 76.62,30.71 76.77,30.57 76.77,29.73 75.3,29.73 75.3,28.85 73.89,28.85 73.76,28.73 71.15,28.73 71.15,31.32 74.91,31.32 75.29,31.7 76.31,31.7
VCC_12V on BOTTOM (solid shape): 11.16,118.27 11.16,115.59 8.12,115.59 7.79,115.26 6.77,115.26 6.77,116.2 6.72,116.25 6.44,116.25 6.31,116.37 6.31,117.23 7.78,117.23 7.78,118.08 8.99,118.08 9.21,118.31 11.13,118.31
VCC_12V on BOTTOM (solid shape): 11.93,162.58 11.93,159.99 8.12,159.99 7.79,159.66 6.77,159.66 6.77,160.6 6.72,160.65 6.39,160.65 6.31,160.72 6.31,161.63 7.78,161.63 7.78,162.43 9.2,162.43 9.47,162.7 11.8,162.7
VCC_12V on BOTTOM (solid shape): 11.93,139.11 11.93,136.52 8.12,136.52 7.79,136.19 6.77,136.19 6.77,137.13 6.72,137.18 6.44,137.18 6.31,137.3 6.31,138.16 7.78,138.16 7.78,138.99 9.09,138.99 9.34,139.24 11.8,139.24
VCC_12V on BOTTOM (solid shape): 76.31,69.06 76.36,69.01 76.65,69.01 76.77,68.9 76.77,68.03 75.3,68.03 75.3,67.13 73.94,67.13 73.76,66.96 71.28,66.96 71.15,67.08 71.15,69.67 74.96,69.67 75.29,70 76.31,70
VCC_12V on BOTTOM (solid shape): 76.31,88.37 76.36,88.32 76.62,88.32 76.62,88.25 76.77,88.1 76.77,87.33 75.3,87.33 75.3,86.44 74.19,86.44 74.02,86.26 72.31,86.26 72.12,86.45 72.12,88.74 72.36,88.98 74.96,88.98 75.29,89.31 76.31,89.31
VCC_12V on BOTTOM (solid shape): 73.25,51.16 73.25,50.55 73.63,50.16 74.9,50.16 75.29,50.56 76.31,50.56 76.31,49.62 76.36,49.57 76.64,49.57 76.77,49.44 76.77,48.58 75.3,48.58 75.3,47.7 73.9,47.7 73.71,47.51 71.48,47.51 71.48,51.41 73,51.41
VCC_12V on BOTTOM (solid shape): 10.04,94.62 9.86,94.44 9.8,94.19 9.8,94.03 9.8,94.03 9.67,94.03 9.67,93.92 8.12,93.92 7.79,93.59 6.77,93.59 6.77,94.53 6.72,94.58 6.46,94.58 6.46,94.59 6.31,94.73 6.31,95.56 7.78,95.56 7.78,96.42 8.97,96.42 9.19,96.64 10.04,96.64
VCC_12V on TOP: 51.14,21.72 41.36,21.72 41.36,17.25 51.14,17.25
VCC_12V on BOTTOM: 74.96,108.29 75.29,108.62 76.05,108.62 76.05,107.75 76.16,107.63 76.82,107.63 76.89,107.56 76.89,106.57 75.52,106.57 75.39,106.44 75.39,105.82 74.1,105.82 73.86,105.58 71.48,105.58 71.48,109.5 73.15,109.5 73.38,109.27 73.38,108.69 73.77,108.29
VCC_12V on BOTTOM: 75.13,147.83 75.52,148.21 76.31,148.21 76.31,147.27 76.36,147.22 76.82,147.22 76.89,147.14 76.89,146.15 75.52,146.15 75.39,146.03 75.39,145.16 71.48,145.16 71.48,148.58 73.31,148.58 74.07,147.83
VCC_12V on BOTTOM: 74.96,127.84 75.29,128.17 76.31,128.17 76.31,127.23 76.36,127.18 76.82,127.18 76.89,127.1 76.89,126.11 75.52,126.11 75.39,125.99 75.39,125.35 73.86,125.35 73.63,125.12 71.7,125.12 71.7,128.98 73.13,128.98 73.38,128.73 73.38,128.27 73.81,127.84
VCC_12V on BOTTOM: 74.96,167.51 75.29,167.84 76.31,167.84 76.31,166.91 76.36,166.85 76.82,166.85 76.89,166.78 76.89,165.79 75.52,165.79 75.39,165.66 75.39,164.95 74.14,164.95 73.99,164.8 71.48,164.8 71.48,168.12 73.1,168.12 73.71,167.51
VCC_12V on BOTTOM: 60.83,21.72 43.97,21.72 43.65,21.4 41,21.4 41,19.94 44.6,19.94 44.6,17.34 45.71,17.34 46.71,18.33 49.37,18.33 51.64,16.07 51.64,14.38 64.9,14.38 64.9,17.65
VCC_12V on L04_PWR1: 40.92,164.01 28.19,164.01 27.72,163.54 27.72,159.88 14.08,146.24 14.08,111.61 17.13,111.61 17.13,96.22 16.39,95.49 12.3,95.49 9.96,93.14 1.56,93.14 1.56,189.28 82.14,189.28 82.14,1.08 41.51,1.08 41.51,22.1 52.25,22.1 52.25,20.41 60.21,20.41 64.4,24.6 64.4,107.95 53.62,118.73 53.62,151.31 ; 8 cut-outs
VCC_12V on L6_SIG2: 57.15,21.72 41.36,21.72 41.36,17.23 45.5,17.23 46.48,16.26 60.58,16.26 60.58,18.29
VCC_12V/20V_HDR on TOP: 17.27,5.28 17.27,16.22 26.72,16.22 26.72,5.28
VCC_12V/20V_HDR on BOTTOM: 17.27,5.28 17.27,17.27 19.77,17.27 19.77,19.08 24.84,19.08 24.84,5.28
VCC_12V/20V_HDR on L03_SIG1: 17.26,5.28 17.26,14.23 27.28,14.23 27.28,5.28
VCC_12V/20V_HDR on L04_PWR1: 17.27,5.29 17.27,14.23 36.88,14.23 36.88,5.29
VCC_12V_EXP_CONN on TOP: 70.08,12.95 70.08,1.07 82.14,1.07 82.14,12.95
VCC_12V_EXP_CONN on TOP: 56.98,29.45 54.85,29.45 54.44,29.85 54.44,31.33 52.95,31.33 52.95,23.37 58.8,23.37 58.8,24.26 58.59,24.47 57.4,24.47 56.98,24.89
VCC_12V_EXP_CONN on TOP: 56.42,84.97 56.42,75.57 59.53,75.57 60.71,76.74 60.71,77.34 60.17,77.88 60.17,80.19 59.31,81.05 59.31,81.79 57.24,83.86 57.24,84.97
VCC_12V_EXP_CONN on L03_SIG1: 58.58,80.55 59.69,81.66 62.46,81.66 68.73,75.39 68.73,61.83 70.01,60.54 70.01,41.83 69.99,41.8 69.99,21.14 68.76,19.92 68.76,16.72 72.52,12.97 82.14,12.97 82.14,1.03 52.95,1.03 52.95,23.81 54.6,23.81 56.52,25.72 60.09,25.72 63.64,29.27 63.64,72.13 58.58,77.18
VCC_12V_EXP_CONN on L04_PWR1: 52.95,25.42 52.95,21.05 59.96,21.05 66.3,27.38 66.3,80.56 58.58,80.56 58.58,77.01 61.19,74.4 61.19,29.22 57.39,25.42
VCC_12V_EXP_CONN on L6_SIG2: 52.95,27.22 52.95,22.35 57.54,22.35 61.21,18.67 61.21,8.26 79.88,8.26 79.88,12.95 74.54,12.95 73.66,13.84 73.66,21.9 68.33,27.22
VCC_CSI_IO on TOP: 40.19,92.16 40.19,90.13 40.68,89.65 43.72,89.65 43.72,92.16
VCC_CSI_IO on TOP: 40.74,35.04 40.74,37.65 34.61,37.65 34.61,49.29 37.21,51.89 52.1,51.89 52.1,57.77 49.83,57.77 49.83,55.04 41.44,55.04 41.44,56.98 35.77,56.98 31.78,52.98 31.78,50.51 29.62,48.36 20.57,48.36 20.43,48.22 5.08,48.22 5.08,72.34 6.87,74.13 6.87,82 11.28,86.41 11.28,94.48 1.03,94.48 1.03,16.91 35.32,16.91 35.32,35.04
VCC_CSI_IO on L04_PWR1: 6.1,89.41 13.34,89.41 13.34,75.95 13.58,75.7 26.07,75.7 40.21,89.84 40.21,92.71 42.79,92.71 42.79,90.02 42.41,89.64 42.41,84.98 30.39,72.97 6.1,72.97
VDD1V8_P_HUB1 on TOP: 24.05,105.97 25.32,105.97 25.32,106.72 25.7,107.11 25.7,109.5 25.37,109.84 24.52,109.84 24.4,109.72 24.4,107.32 24.05,106.97
VDD1V8_P_HUB2 on TOP: 33.01,76.59 34.45,76.59 34.45,70.52 33.49,70.52 33.49,73.11 33.01,73.59
VDD1V8_P_HUB3 on TOP: 6.92,50.2 6.92,49.01 20.58,49.01 27.91,56.34 27.91,71.02 26.44,71.02 26.44,61.71 18.39,53.65 8.11,53.65 8.11,50.2
VDD11_CSI_HUB1 on BOTTOM (solid shape): 24.06,145.06 21.75,145.06 21.75,146.64 20.81,146.64 20.81,148.14 24.06,148.14
VDD11_CSI_HUB1 on TOP: 32.59,111.53 34.29,111.53 34.29,106.93 32.59,106.93
VDD11_CSI_HUB1 on BOTTOM: 32.62,111.81 32.62,107.65 34.29,107.65 34.29,111.81
VDD11_CSI_HUB1 on L04_PWR1: 22.1,144.22 23.16,144.22 23.16,148.19 14.08,148.19 14.08,111.67 25.18,111.67 25.18,110.07 25.65,109.6 31.5,109.6 32.13,108.97 32.13,108.44 32.88,107.7 34.94,107.7 34.94,119.1 22.1,119.1
VDD11_CSI_HUB2 on BOTTOM (solid shape): 30.42,44.55 28.68,44.55 28.68,46.32 28.23,46.77 27.39,46.77 27.39,48.23 30.42,48.23
VDD11_CSI_HUB2 on L04_PWR1: 26.76,72.91 26.76,45.87 31.66,45.87 31.66,59.34 35.9,59.34 35.9,68.89 42.21,68.89 42.21,72.91
VDD11_CSI_HUB3 on TOP: 17.1,49.74 17.1,46.31 18.59,46.31 18.59,49.74
